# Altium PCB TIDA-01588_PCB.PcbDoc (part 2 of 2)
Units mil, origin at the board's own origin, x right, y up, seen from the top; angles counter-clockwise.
Board outline 787.4 x 472.44 mil, 2 copper layers (Top Layer, Bottom Layer), stack 62 mil thick; 49 components, 26 nets, 145 pads, 54 vias.
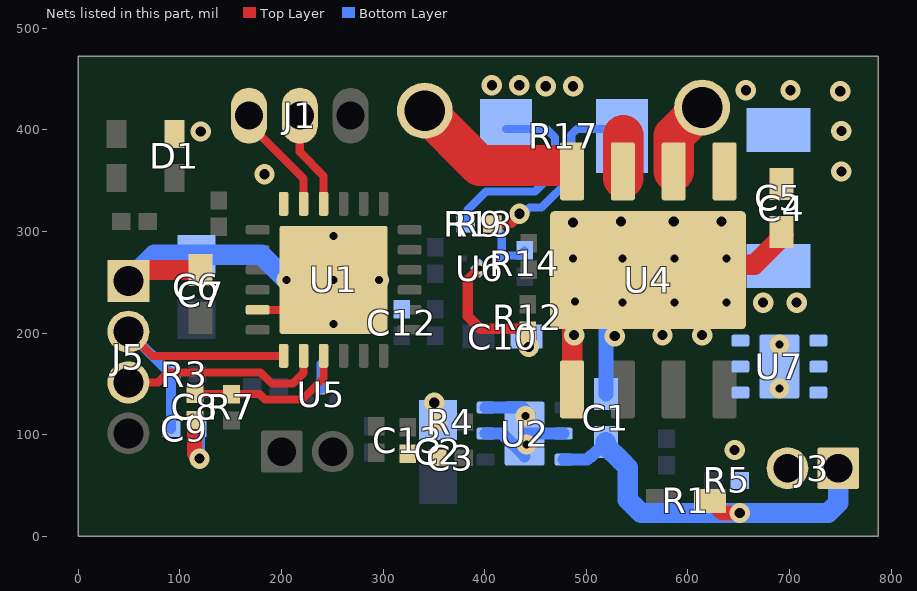
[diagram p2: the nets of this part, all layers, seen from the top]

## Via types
v1: diameter 20, hole 10, Top Layer to Bottom Layer, tented both sides, 28 vias
v2: diameter 19.68, hole 7.87, Top Layer to Bottom Layer, 17 vias
v3: diameter 20, hole 10, Top Layer to Bottom Layer, 8 vias
v4: diameter 12, hole 6, Top Layer to Bottom Layer, 1 vias

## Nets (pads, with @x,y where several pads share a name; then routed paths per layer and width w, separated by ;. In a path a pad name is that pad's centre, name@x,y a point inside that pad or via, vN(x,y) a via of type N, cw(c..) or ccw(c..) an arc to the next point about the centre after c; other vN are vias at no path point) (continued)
NetR13_2: R13.2 R14.2 U6.4 | length 64.1
  Bottom Layer w8: R13.2@407.29,307.43 416.81,297.91 416.81,276.36 ; 415.3,273.32 415.3,276.36 416.81,276.36 ; R14.2@439.3,281.42 434.25,276.36 416.81,276.36
OUT1: pad.1@614,422 U4.6 | length 74.3
  Top Layer w40: U4.6@586,359.28 586,394 pad.1@614,422
OUT2: pad.1@341,419 U4.8 | length 152.7
  Top Layer w40: pad.1@341,419 395,365 471.3,365
"POT / ENC_A": C8.1 R7.2 U1.3 | length 160
  Top Layer w8: C8.1@114.7,140.49 115.24,139.95 R7.2@150.7,139.95 178.45,139.95 183.85,134.55 220.43,134.55 241.46,155.58 U1.3@241.46,177.62
RST: C9.1 J5.2 R3.1 U1.1 | length 275.7
  Top Layer w8: J5.2@49.3,201.43 73.1,177.62 U1.1@202.09,177.62
  Bottom Layer w10: J5.2@49.3,201.43 R3.1@91.31,159.43 C9.1@91.31,105.8
RXD: J1.2 U1.16 | length 100.5
  Top Layer w8: J1.2@218,418 J1.2@218,414 218,378.21 241.46,354.76 U1.16@241.46,327.23
SENSE+: R13.1 R17.2 U4.7 | length 243.8
  Top Layer w40: U4.7@536.3,352.36 536.3,394.8
  Bottom Layer w8: R13.1@381.31,307.43 383.18,309.29 383.18,321.37 401.23,339.43 449.43,339.43 469.3,359.3 469.3,392.43 460.93,400.8 R17.2@421.13,400.8
  other v1: 460,443 487,443 407,444 434,444
SENSE-: C1.2 C2.1 C3.2 C4.1 C5.2 C6.2 C7.2 C8.2 C9.2 C10.2 C12.2 C13.2 D1.2 J3.2 J5.1 R4.1 R5.1 R9.1 R12.1 R17.1 U1.18 U1.23 U1.25@251.3,252.43 U2.2 U2.3 U2.5 U2.7@439.3,101.08 U4.1 U4.9@560.7,261.92 U5.1 U6.3 U7.1 U7.2 U7.3 U7.7@690,167 | length 1216.8
  Top Layer w8: U1.23@176.5,222.9 221.77,222.9 v2(251.3,252.43) ; R9.1@407.29,307.43 426.3,307.43 v1@434.3,315.43
  Top Layer w10: U1.25@229.99,226.1 U1.25@259.51,255.62 ; v4@395.16,263.88 383.3,252.02 383.3,216.5 395.55,204.25 440.49,204.25 R12.1@442.3,202.43
  Top Layer w15: C8.2@114.7,114.51 114.7,81.03 v1(119.3,76.43) ; R12.1@442.3,202.43 443.3,201.43 v1(443.3,186.5)
  Top Layer w20: J5.1@49.3,251.43 J5.1@58.92,261.05 ; J5.1@54.92,262.05 C7.2@120.3,262.05 ; U4.1@486.3,137.8 U4.9@486.3,221.66 ; U4.9@637.07,267.17 665.29,267.17 C4.1@694.3,296.18
  Bottom Layer w8: v1@434.3,315.43 v1@436.3,317.43 ; v1(434.3,317.43) v1@436.3,317.43 ; R17.1@535.3,400.8 490.67,400.8 485.18,395.3 485.18,352.73 456,323.55 444.13,323.55 438,317.43 v1@436.3,317.43
  Bottom Layer w10: U5.1@239.3,145.4 239.3,169.34 240.92,170.95
  Bottom Layer w12: v2(251.3,209.12) 251.59,209.41 280.3,209.41 ; U2.2@400.92,101.08 417.02,101.08 U2.7@439.3,78.8 ; U2.3@400.92,126.67 437.13,126.67 444.3,119.5 443.3,118.5 v2(440.3,118.5) ; U2.7@439.3,101.08 U2.5@477.69,101.08
  Bottom Layer w15: C9.2@117.29,105.8 117.29,78.43 v1(119.3,76.43) ; C1.2@519.3,140.12 519.3,207.02 v2@535.71,223.43
  Bottom Layer w20: J5.1@49.3,251.43 74.87,276.99 C6.2@116.3,276.99 180.26,276.99 v2(204.9,252.36)
  other v1: 646,85 350.3,131.5 674,230 707,230 183.3,356.43 120.52,398.48
  other v2: 441.3,90.5 690,145.35 690,188.65 535.41,230.35 586.59,230.35 637.77,230.35 489,231 295.9,252.36 487,273.35 535.41,273.65 586.59,273.65 637.77,273.65 251.3,295.73
  other v3: 528,197 488,198 575,198 614,198 487,309 534,310 586,310 633,310
  other v4: 395,263.72
TEST: J5.3 U1.2 | length 202.2
  Top Layer w8: J5.3@49.3,151.43 78.31,151.43 88.3,161.42 179.43,161.42 190.42,150.43 211.3,150.43 221.77,160.9 U1.2@221.77,177.62
TXD: J1.1 U1.17 | length 109
  Top Layer w8: J1.1@168,414 168,405.76 221.77,351.99 U1.17@221.77,327.23
VM: C1.1 C4.2 C5.1 J3.1 R1.2 U2.6 U4.5 U7.4 U7.5 U7.6 | length 398.1
  Top Layer w15: R1.2@621.62,35 633.62,23 v1(651,23)
  Bottom Layer w12: U2.6@477.69,75.49 500.73,75.49 504.11,78.87 505.11,78.87 C1.1@519.11,92.88
  Bottom Layer w20: C1.1@519.11,92.88 519.11,89.31 533.71,74.71 ; 534.87,73.71 540.87,67.71 540.87,35.91 553.79,23 v1(651,23) 738,23 748,33 J3.1@748,67
  other v1: 751,359 751,399 750,438 657,439 701,439
pads on no net: U1.7 U1.11 U1.12 U1.13 U1.14 U1.15 U1.19 U1.20 U1.21 U1.22 U1.25@223.94,225.06 U1.25@223.94,279.79 U1.25@278.66,225.06 U1.25@278.66,279.79 U2.4 U2.7@439.3,83.36 U2.7@439.3,118.8 U4.9@561,252 U7.7@690,149.28 U7.7@690,184.72

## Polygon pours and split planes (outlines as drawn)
SENSE- on Bottom Layer "Top Layer-No Net" (solid, pour order 20): 359.74,466 373,452.74 373,355.43 408.55,355.43 441.43,322.55 446.3,317.68 446.3,276.43 446.3,221.43 457.3,210.43 458.05,209.68 458.05,198.43 490.05,166.43 508.3,166.43 553.3,166.43 571.3,148.43 571.3,47.43 562.3,38.43 532.44,8.56 299.21,8.56 11.19,8.56 0.3,21.71 0.3,452.7 13.6,466
SENSE- on Bottom Layer "Top Layer-No Net" (solid, pour order 24): 514.3,238.43 514.3,154.43 525.3,143.43 527.66,141.06 559.26,141.06 578.94,141.06 596.3,158.43 596.3,177.43 596.3,227.43 589.3,234.43 578.3,245.43 550.3,245.43 521.3,245.43
SENSE- on Bottom Layer "Top Layer-No Net" (solid, pour order 18): 510.36,428.77 510.36,347.7 458.93,296.27 458.93,212.49 495.01,176.42 510.36,176.42 644.78,42 721.73,42 721.73,250.19 722,358 715.97,364.48 641.52,364.48 577.23,428.77
VM on Bottom Layer "BOTTOM_LAYER_VM_P010" (solid, remove dead copper, pour order 10): 646,380 713.4,380 727.3,366.1 727.3,209.3 718,200 718,64 737,45 767,45 773,51 773,453 762,464 639,464 639,387
VM on Top Layer "TOP_LAYER_VM_P004" (solid, remove dead copper, pour order 4): 617.3,336.7 623,331 768,331 774.72,337.72 774.72,458.28 770,463 628,463 617.3,452.3
SENSE- on Top Layer "TOP_LAYER_SENSE-_P014" (solid, remove dead copper, pour order 14): 0.3,452.7 0.3,29.7 18,12 774,12 787.7,25.7 787.7,448.3 770,466 13.6,466

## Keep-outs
Keep-Out Layer:
  lines w6: 10,10 777.4,10 778,463 10.6,463 10,10

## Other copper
Top Layer:
  pour cut-out: 462.3,207.63 462.3,154.57 459.16,151.43 426.3,151.43 405.3,172.43 405.3,205.3 413.43,213.43 456.51,213.43
  region net SENSE+: 395,452 399,456 546,456 556,446 556,361 551,356 519,356 519,360 517,362 517,386.73 502.93,400.8 405.2,400.8 395,411
  pour cut-out: 442,329.13 442,308.06 462.74,328.8 452.21,339.34
  text ".Layer_Name" at -361.6,-2171.42 h60
Bottom Layer:
  region net SENSE+: 396,364 401.43,358.57 442.57,358.57 446,362 446,422 494,422 501,429 501,456 399,456 396,453
  text ".Layer_Name" at -361.6,-2171.42 h60

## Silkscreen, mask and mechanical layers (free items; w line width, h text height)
Top Overlay:
  lines w6: 294.3,62.43 294.3,66.43 ; 324.3,124.43 324.3,126.43 ; 419.59,249.28 422.41,249.28 427.55,254.43
  text "+10.8V" at 768,122 h25 r90
  text "GND" at 731.34,119.76 h25 r90
  text ".Layer_Name" at -361.6,-2171.42 h60
Bottom Overlay:
  lines w6: 270,118 270,114 272,112 ; 330.3,167.43 348.3,167.43 353.3,172.43 353.3,180.43 ; 373,345 376,342 376,321 ; 422.3,294.43 429.3,301.43 437.57,301.43 ; 457.3,249.43 601.3,249.43 611.3,259.43 616,264.13 616,318 ; 534.3,58.43 541.3,51.43 544.3,51.43
  text ".Layer_Name" at -361.6,-2171.42 h60
Top Paste:
  text ".Layer_Name" at -361.6,-2171.42 h60
Bottom Paste:
  text ".Layer_Name" at -361.6,-2171.42 h60
Top Solder:
  text ".Layer_Name" at -361.6,-2171.42 h60
  text ".Layer_Name" at -361.6,-2171.42 h60
Bottom Solder:
  text ".Layer_Name" at -361.6,-2171.42 h60
Drill Guide:
  text ".Layer_Name" at -361.6,-2171.42 h60
M1 Board Outline:
  the board outline again, w6
M2 Board Dimensions:
  rectangle: -938.6,-1587.93 -813.6,-1462.93
  rectangle: -813.6,-1712.93 -438.6,-1587.93
  lines w7: -938.6,-1587.93 61.4,-1587.93 ; -813.6,-1712.93 -813.6,-1462.93 ; -688.6,-1712.93 -688.6,-1462.93 ; -438.6,-1712.93 -438.6,-1462.93 ; -188.6,-1712.93 -188.6,-1462.93 ; -938.6,-1712.93 61.4,-1712.93 61.4,-1462.93 -938.6,-1462.93 -938.6,-1712.93
M3 3D STEP Top:
  text ".Layer_Name" at -361.6,-2171.42 h60
M4 3D STEP Bottom:
  text ".Layer_Name" at -361.6,-2171.42 h60
M5 Assembly Top:
  circle w6: c49.3,251.5 r10.63
  circle w6: c192.3,398.5 r9.9
  lines w10: -1230.6,-2243.1 5369.4,-2243.1 ; -1230.6,-2039.76 5371.4,-2039.76 ; -1230.6,-1836.43 -1230.6,-2446.43 2774.4,-2446.43 5371.4,-2446.43 5371.4,-1836.43 -1230.1,-1836.43 -1230.1,-2446.43 345.4,-2446.43 ; 1234.4,-2446.43 1234.4,-1836.43 ; 2501.4,-2039.76 2501.4,-1836.43 ; 3341.4,-2039.76 3341.4,-1836.43 ; 3963.4,-2452.93 3963.4,-2250.1
  text "COMPONENTS MARKED 'DNP' SHOULD NOT BE POPULATED." at 214.9,-1631.43 h60
  text "ASSEMBLY VARIANT:" at 214.4,-1746.93 h60
  text ".VariantName" at 1250.4,-1746.93 h60
  text "PCB VIEWED FROM TOP SIDE" at -1167.1,-1968.6 h60
  text "BOARD #:" at 1309.4,-1968.6 h60
  text ".PRJ_Number" at 1854.9,-1968.6 h60
  text "REV:" at 2699.4,-1968.6 h60
  text ".PCB_Rev" at 2990.9,-1968.6 h30
  text "SVN REV:" at 3537.4,-1968.6 h60
  text ".VersionControl_RevNumber" at 4043.4,-1968.6 h30
  text ".Layer_Name" at -367.6,-2165.42 h60
  text "TID #:" at 1309.4,-2171.93 h60
  text ".TID" at 1854.9,-2171.93 h60
  text "PLOT NAME =" at -1167.1,-2377.26 h60
  text ".plot_File_Name" at -361.6,-2377.26 h60
  text "GENERATED    :" at 1311.4,-2377.26 h60
  text ".Print_Date" at 2180.9,-2377.26 h60
  text ".Print_Time" at 2909.9,-2377.26 h60
  text "TEXAS INSTRUMENTS" at 4174.4,-2377.26 h60
M6 Assembly Bottom:
  lines w10: -1231.1,-2040.26 5370.9,-2040.26 ; -1229.1,-2243.6 5370.9,-2243.6 ; 176.9,-2453.43 176.9,-2250.6 ; 798.9,-2040.26 798.9,-1836.93 ; 1638.9,-2040.26 1638.9,-1836.93 ; 2905.9,-2446.93 2905.9,-1836.93 ; 3794.9,-2446.93 5370.4,-2446.93 5370.4,-1836.93 -1231.1,-1836.93 -1231.1,-2446.93 1365.9,-2446.93 5370.9,-2446.93 5370.9,-1836.93
  text "COMPONENTS MARKED 'DNP' SHOULD NOT BE POPULATED." at 5163.4,-1630.93 h60
  text ".VariantName" at 4119.4,-1746.93 h60
  text "ASSEMBLY VARIANT:" at 5158.4,-1746.93 h60
  text ".VersionControl_RevNumber" at 96.9,-1969.1 h60
  text "SVN REV:" at 602.9,-1969.1 h60
  text ".PCB_Rev" at 1149.4,-1969.1 h60
  text "REV:" at 1440.9,-1969.1 h60
  text ".PRJ_Number" at 2285.4,-1969.1 h60
  text "BOARD #:" at 2830.9,-1969.1 h60
  text "PCB VIEWED FROM BOTTOM SIDE" at 5307.4,-1969.1 h60
  text ".Layer_Name" at 4924,-2165 h60
  text ".TID" at 2285.4,-2172.43 h60
  text "TID #:" at 2830.9,-2172.43 h60
  text "TEXAS INSTRUMENTS" at -34.1,-2377.76 h60
  text ".Print_Time" at 1230.4,-2377.76 h60
  text ".Print_Date" at 1959.4,-2377.76 h60
  text "GENERATED    :" at 2828.9,-2377.76 h60
  text ".plot_File_Name" at 4501.9,-2377.76 h60
  text "PLOT NAME =" at 5307.4,-2377.76 h60
M9 Title Sheet:
  drawing of 57 lines, arcs and shapes, not listed
  text "1" at -198.76,6723.57 h70
  text "2" at 2296.9,6723.57 h70
  text "3" at 4786.24,6723.57 h70
  text "4" at 7292.91,6723.57 h70
  text "5" at 9791.9,6723.57 h70
  text "6" at 12296.9,6723.57 h70
  text "A" at -1355.1,5580.57 h70
  text "A" at 13444.9,5580.57 h70
  text "B" at -1355.1,3200.57 h70
  text "B" at 13444.9,3200.57 h70
  text "C" at -1355.1,825.57 h70
  text "C" at 13444.9,825.57 h70
  text "PROJECT TITLE:" at 10404.9,-1035.43 h45
  text ".PRJ_Title" at 10454.9,-1168.76 h70
  text "DESIGNED FOR:" at 10404.9,-1336.43 h45
  text ".PRJ_Customer" at 10454.9,-1476.43 h70
  text "D" at -1355.1,-1544.43 h70
  text "D" at 13444.9,-1544.43 h70
  text "FILE NAME:" at 10404.9,-1636.43 h45
  text ".PCB_File_Name_No_Path" at 10454.9,-1756.43 h70
  text "Texas Instruments (TI) and/or its licensors do not warrant the accuracy or completeness of this specification" at 5435.4,-1918.27 h45
  text "ENGINEER:" at 10404.9,-1926.43 h45
  text "LAYOUT BY:" at 11909.9,-1926.43 h45
  text "or any information contained therein. TI and/or its licensors do not warrant that this design will meet" at 5390.42,-2030.93 h45
  text ".PRJ_Engineer" at 10454.9,-2081.42 h70
  text ".PCB_Layout" at 11960.4,-2081.42 h70
  text "the specifications, will be suitable for your application or fit for any particular purpose, or will operate in" at 5390.42,-2143.6 h45
  text "ALTIUM DESIGNER VERSION:" at 11909.9,-2236.43 h45
  text "an implementation. TI and/or its licensors do not warrant that the design is production worthy. You should" at 5390.42,-2256.26 h45
  text "completely validate and test your design implementation to confirm the system functionality for your application." at 5435.4,-2368.93 h45
  text ".print_Scale" at 10454.9,-2369.76 h70
  text ".Application_BuildNumber" at 11960.4,-2369.76 h70
  text "1" at -198.76,-2576.43 h70
  text "2" at 2296.9,-2576.43 h70
  text "3" at 4786.24,-2576.43 h70
  text "4" at 7292.91,-2576.43 h70
  text "5" at 9791.9,-2576.43 h70
  text "6" at 12296.9,-2576.43 h70
M10 Fab Notes:
  drawing of 189 lines, arcs and shapes, not listed
  text "DESIGN INFORMATION" at 11443.42,5043.25 h60
  text "MIN. TRACK WIDTH:" at 10798.86,4911.12 h60
  text "8" at 11895.1,4911.12 h60
  text "MIL" at 12049.86,4911.12 h60
  text "MIN. CLEARANCE:" at 10798.86,4786.99 h60
  text "4.11" at 11835.1,4787 h60
  text "MIL" at 12049.86,4786.99 h60
  text "MIN. VIA PAD SIZE:" at 10798.86,4662.87 h60
  text "MIL" at 12049.86,4662.87 h60
  text "14" at 11857.11,4654.87 h60
  text "3 mil" at 11547,4526 h60
  text "MINIMUM ANNULAR RING" at 10469.63,4524.75 h60
  text "EXTERNAL" at 12201.86,4524.75 h60
  text "PER" at 10669.63,4414.62 h60
  text "IPC-D-275 CLASS 2 LEVEL C" at 10889.63,4414.62 h60
  text "MIL, HOLES" at 12377.86,4314.14 h60
  text "+/-" at 11985.4,4305.55 h60
  text "+/-" at 12839.4,4305.55 h60
  text "REGISTRATION TOLERANCES:" at 10469.63,4304.49 h60
  text "METAL" at 11669.4,4304.49 h60
  text "5" at 12245.6,4304.49 h60
  text "3" at 13078.6,4304.49 h60
  text "MIL" at 13194.86,4304.49 h60
  text "HOLE SIZE TOLERANCE (UNLESS OTHERWISE SPECIFIED):" at 10469.63,4206.17 h60
  text "+/-" at 12839.4,4203.3 h60
  text "3" at 13078.6,4202.24 h60
  text "MIL" at 13194.86,4202.24 h60
  text "MATERIAL:" at 10394.86,4064.59 h60
  text "FR-4 High Tg" at 11381.3,3936.07 h60
  text "X" at 11236.87,3928.08 h60
  text "FR-408" at 10815.86,3923.56 h60
  text "OTHER" at 12303.86,3923.56 h60
  text "63 MIL (1.6mm) +/-10%" at 11135.96,3780.53 h60
  text "X" at 11015.87,3778.08 h60
  text "THICKNESS:" at 10469.63,3772.31 h60
  text "OTHER" at 12420.86,3772.31 h60
  text "TOLERANCE:" at 10469.63,3633.99 h60
  text "X" at 11317.87,3633.99 h60
  text "ANSI IPC-6012 TYPE 3 CLASS 2" at 11495.88,3633.99 h60
  text "OTHER +/-" at 11495.86,3489.8 h60
  text "BOW & TWIST:" at 10469.63,3344.62 h60
  text "X" at 11317.87,3344.62 h60
  text "ANSI IPC-6012 TYPE 3 CLASS 2" at 11495.88,3344.62 h60
  text "OTHER +/-" at 11495.86,3197.92 h60
  text "DRILLING:" at 10394.86,3067.3 h60
  text "NC_DRILL FILES" at 12155.86,2962.11 h60
  text "REFERENCE:" at 10469.63,2958.17 h60
  text "X" at 11126.87,2958.08 h60
  text "AS SHOWN" at 11304.86,2958.17 h60
  text "X" at 12027.87,2958.17 h60
  text "OTHER" at 12453.86,2815.92 h60
  text "PTH COPPER THICKNESS:" at 10469.31,2812.39 h60
  text "X" at 11608.54,2812.39 h60
  text "20-30 um" at 11736.54,2812.39 h60
  text "BOARD FINISH:" at 10394.86,2664.8 h60
  text "SILKSCREEN:" at 10550.08,2554.67 h60
  text "X" at 11507.87,2554.67 h60
  text "TOP" at 11624.86,2554.67 h60
  text "X" at 12017.87,2554.67 h60
  text "BOTTOM" at 12135.86,2554.67 h60
  text "SILKSCREEN COLOR:" at 10550.08,2399.48 h60
  text "X" at 11506.87,2399.48 h60
  text "WHITE" at 11624.86,2399.48 h60
  text "OTHER" at 12135.86,2399.48 h60
  text "X" at 11637.87,2256.03 h60
  text "GREEN" at 11755.86,2256.03 h60
  text "OTHER" at 12373.86,2256.03 h60
  text "SOLDER RESIST COLOR:" at 10550.08,2249.17 h60
  text "X" at 11637.87,2101.78 h60
  text "MATTE" at 11755.86,2101.78 h60
  text "SEMI-GLOSS" at 12373.4,2101.14 h60
  text "IMMERSION GOLD (ENIG)" at 11455.86,1929.01 h60
  text "ENEPIG" at 12793.4,1921.79 h60
  text "SURFACE FINISH:" at 10394.86,1920.79 h60
  text "X" at 11277.87,1920.79 h60
  text "IMM. TIN/SILVER OR EQUIV" at 10724.4,1783.47 h60
  text "OTHER" at 12155.86,1779.54 h60
  text "ARRAY/PANEL:" at 10394.86,1624.16 h60
  text "CUT AND TRIM PER M1 BOARD OUTLINE" at 11455.86,1615.94 h60
  text "N.C. ROUTE" at 11455.86,1479.97 h60
  text "X" at 12143.87,1479.97 h60
  text "V. SCORE" at 12321.86,1479.97 h60
  text "CERTIFICATION:" at 10394.86,1350.84 h60
  text "MATERIALS AND WORKMANSHIP FOR ALL PCBS" at 11119.86,1350.84 h60
  text "TO MEET OR EXCEED THE REQUIREMENTS OF:" at 11119.86,1256.78 h60
  text "X" at 10757.37,1128.15 h60
  text "ANSI IPC-A-600F CLASS ->" at 10885.36,1128.15 h60
  text "X" at 12533.37,1128.15 h60
  text "2" at 12643.36,1128.15 h60
  text "1" at 12328.37,1126.65 h60
  text "3" at 12997.36,1126.65 h60
  text "X" at 11569.37,980.47 h60
  text "RoHS" at 11697.37,980.47 h60
  text "OTHER" at 12341.77,980.47 h60
  text "PER ORDER" at 12738.82,980.47 h60
  text "ALL BOARDS MUST MEET OR EXCEED UL94-V0 REQUIREMENTS." at 10422.4,826.64 h60
  text "PCB MUST BEAR THE UL94V-0 UL REGISTERED MATERIAL ID NUMBER" at 10422.4,710.57 h60
  text "ADDITIONAL REQUIREMENTS:" at 10394.86,541.15 h60
  text "MICROSECTION:" at 10469.63,434.02 h60
  text "YES" at 11375.36,434.02 h60
  text "REQUIRED" at 12236.86,289.69 h60
  text "BARE BOARD ELEC. TEST:" at 10469.63,286.84 h60
  text "NONE" at 11775.36,286.84 h60
  text "X" at 12118.87,286.84 h60
  text "PER ORDER" at 12828.86,286.84 h60
  text "XX MIL VIAS REQUIRE NON-CONDUCTIVE FILL AND PLANARIZE" at 10637.78,81.89 h59
  text "XX MIL VIAS REQUIRE CONDUCTIVE FILL AND PLANARIZE" at 10645.78,-22.09 h60
  text "OUTER XX MIL VIAS REQUIRE 50 OHM SINGLE-ENDED IMPEDANCE" at 10644.79,-185.47 h58
  text "LAYER 2 & 3 (INNER LAYERS) XX MIL WIDE, XX MIL SPACE / TRACES REQUIRE 100 OHM DIFFERENTIAL IMPEDANCE" at 10636.79,-421.18 h60
M11 Gerber Information:
  lines w10: -1230.6,-2243.1 5369.4,-2243.1 ; -1230.6,-2039.76 5371.4,-2039.76 ; -1230.6,-1836.43 -1230.6,-2446.43 2774.4,-2446.43 5371.4,-2446.43 5371.4,-1836.43 -1230.1,-1836.43 -1230.1,-2446.43 345.4,-2446.43 ; 1234.4,-2446.43 1234.4,-1836.43 ; 2501.4,-2039.76 2501.4,-1836.43 ; 3341.4,-2039.76 3341.4,-1836.43 ; 3963.4,-2452.93 3963.4,-2250.1
  text "ALL ARTWORK VIEWED FROM TOP SIDE" at -1167.1,-1968.6 h60
  text "BOARD #:" at 1309.4,-1968.6 h60
  text ".PRJ_Number" at 1854.9,-1968.6 h60
  text "REV:" at 2699.4,-1968.6 h60
  text ".PCB_Rev" at 2990.9,-1968.6 h60
  text "SVN REV:" at 3537.4,-1968.6 h60
  text ".VersionControl_RevNumber" at 4043.4,-1968.6 h60
  text "LAYER NAME =" at -1167.1,-2171.42 h60
  text "TID #:" at 1309.4,-2171.93 h60
  text ".TID" at 1854.9,-2171.93 h60
  text "PLOT NAME =" at -1167.1,-2377.26 h60
  text ".plot_File_Name" at -361.6,-2377.26 h60
  text "GENERATED    :" at 1311.4,-2377.26 h60
  text ".Print_Date" at 2180.9,-2377.26 h60
  text ".Print_Time" at 2909.9,-2377.26 h60
  text "TEXAS INSTRUMENTS" at 4174.4,-2377.26 h60
M12 Stackup:
  drawing of 191 lines, arcs and shapes, not listed
  text "Layer" at 8859.24,6517.07 h60
  text "Name" at 9269.16,6517.07 h60
  text "Material" at 10198.9,6517.07 h60
  text "Thickness" at 11058.67,6517.07 h60
  text "Constant" at 11708.5,6517.07 h60
  text "Board Layer Stack" at 12278.36,6517.07 h60
  text "1" at 8859.24,6397.07 h60
  text "Top Overlay" at 9269.16,6397.07 h60
  text "2" at 8859.24,6277.07 h60
  text "Top Solder" at 9269.16,6277.07 h60
  text "Solder Resist" at 10198.9,6277.07 h60
  text "0.40mil" at 11058.67,6277.07 h60
  text "3.5" at 11708.5,6277.07 h60
  text "3" at 8859.24,6157.07 h60
  text "Top Layer" at 9269.16,6157.07 h60
  text "Copper" at 10198.9,6157.07 h60
  text "1.40mil" at 11058.67,6157.07 h60
  text "4" at 8859.24,6037.07 h60
  text "Dielectric1" at 9269.16,6037.07 h60
  text "FR-4 High Tg" at 10198.9,6037.07 h60
  text "59.20mil" at 11058.67,6037.07 h60
  text "4.8" at 11708.5,6037.07 h60
  text "5" at 8859.24,5917.07 h60
  text "Bottom Layer" at 9269.16,5917.07 h60
  text "Copper" at 10198.9,5917.07 h60
  text "1.40mil" at 11058.67,5917.07 h60
  text "6" at 8859.24,5797.07 h60
  text "Bottom Solder" at 9269.16,5797.07 h60
  text "Solder Resist" at 10198.9,5797.07 h60
  text "0.40mil" at 11058.67,5797.07 h60
  text "3.5" at 11708.5,5797.07 h60
  text "7" at 8859.24,5677.07 h60
  text "Bottom Overlay" at 9269.16,5677.07 h60
M13 Component Bodies Top:
  text ".Layer_Name" at -361.6,-2171.42 h60
M14 Component Bodies Bottom:
  text ".Layer_Name" at -361.6,-2171.42 h60
M15 Courtyards Top:
  text ".Layer_Name" at -361.6,-2171.42 h60
M16 Courtyards Bottom:
  text ".Layer_Name" at -361.6,-2171.42 h60
Drill Drawing:
  circle w10: c1433.62,795.83 r33.33
  lines w10: 1400.29,12.5 1433.62,29.17 1466.96,12.5 1450.29,45.83 1466.96,79.17 1433.62,62.5 1400.29,79.17 1416.96,45.83 1400.29,12.5 ; 1400.29,179.17 1416.96,179.17 1433.62,162.5 1450.29,179.17 1466.96,179.17 1450.29,195.83 1466.96,212.5 1450.29,212.5 1433.62,229.17 1416.96,212.5 1400.29,212.5 1416.96,195.83 1400.29,179.17 ; 1400.29,312.5 1400.29,329.17 1416.96,345.83 1400.29,362.5 1400.29,379.17 1416.96,379.17 1433.62,362.5 1450.29,379.17 1466.96,379.17 1466.96,362.5 1450.29,345.83 1466.96,329.17 1466.96,312.5 1450.29,312.5 1433.62,329.17 1416.96,312.5 1400.29,312.5 ; 1400.29,529.17 1466.96,529.17 1433.62,462.5 1400.29,529.17 ; 1400.29,629.17 1416.96,629.17 1416.96,612.5 1450.29,612.5 1450.29,629.17 1466.96,629.17 1466.96,662.5 1450.29,662.5 1450.29,679.17 1416.96,679.17 1416.96,662.5 1400.29,662.5 1400.29,629.17 ; 1400.29,912.5 1466.96,912.5 1466.96,979.17 1400.29,979.17 1400.29,912.5
  lines w15: 1340.5,-32.5 4815.59,-32.5 ; 1340.5,1017.5 4815.59,1017.5 ; 1891.38,-182.5 1891.38,1167.5 ; 2431.24,-182.5 2431.24,1167.5 ; 3530.92,-182.5 3530.92,1167.5 ; 4036.79,-182.5 4036.79,1167.5 ; 1340.5,-182.5 4815.59,-182.5 4815.59,1167.5 1340.5,1167.5 1340.5,-182.5
  text "This is not an impedance controlled board" at 1458,1281 h60
  text "Symbol" at 1430.5,1062.5 h72
  text "Count" at 1936.38,1062.5 h72
  text "Hole Size" at 2476.24,1062.5 h72
  text "Plated" at 3575.92,1062.5 h72
  text "Hole Type" at 4081.79,1062.5 h72
  text "1" at 1936.38,912.5 h60
  text "6.00mil (0.152mm)" at 2476.24,912.5 h60
  text "PTH" at 3575.92,912.5 h60
  text "Round" at 4081.79,912.5 h60
  text "2" at 1936.38,762.5 h60
  text "40.00mil (1.016mm)" at 2476.24,762.5 h60
  text "PTH" at 3575.92,762.5 h60
  text "Round" at 4081.79,762.5 h60
  text "3" at 1936.38,612.5 h60
  text "27.56mil (0.700mm)" at 2476.24,612.5 h60
  text "PTH" at 3575.92,612.5 h60
  text "Round" at 4081.79,612.5 h60
  text "4" at 1936.38,462.5 h60
  text "28.00mil (0.711mm)" at 2476.24,462.5 h60
  text "PTH" at 3575.92,462.5 h60
  text "Round" at 4081.79,462.5 h60
  text "4" at 1936.38,312.5 h60
  text "29.53mil (0.750mm)" at 2476.24,312.5 h60
  text "PTH" at 3575.92,312.5 h60
  text "Round" at 4081.79,312.5 h60
  text "17" at 1936.38,162.5 h60
  text "7.87mil (0.200mm)" at 2476.24,162.5 h60
  text "PTH" at 3575.92,162.5 h60
  text "Round" at 4081.79,162.5 h60
  text "36" at 1936.38,12.5 h60
  text "10.00mil (0.254mm)" at 2476.24,12.5 h60
  text "PTH" at 3575.92,12.5 h60
  text "Round" at 4081.79,12.5 h60
  text "67 Total" at 1936.38,-137.5 h60
  text "FOR 10MIL DRILL +0/-10MIL" at 1476,-355 h60
  text "FOR 8MIL DRILL +0/-8MIL" at 1474,-459 h60
  text "FOR 7.87MIL DRILL +0/-7.87MIL" at 1475,-563 h60
  text "FOR PTH DRILL +/-3MIL" at 1475,-681 h60
  text "ALL 10 mil drill via are tented" at 1464,-817 h60
  text ".Layer_Name" at -361.6,-2171.42 h60
M17 Embedded Cavity:
  text ".Layer_Name" at -361.6,-2171.42 h60
M18 Embedded Assembly:
  text ".Layer_Name" at -361.6,-2171.42 h60
M19 Embedded Keepout:
  text ".Layer_Name" at -361.6,-2171.42 h60

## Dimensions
0,472.44 to 0,0 on M2 Board Dimensions
0,0 to 787.4,0 on M2 Board Dimensions
-938.6,-1712.93 to 61.4,-1712.93 on M2 Board Dimensions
